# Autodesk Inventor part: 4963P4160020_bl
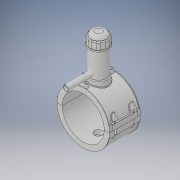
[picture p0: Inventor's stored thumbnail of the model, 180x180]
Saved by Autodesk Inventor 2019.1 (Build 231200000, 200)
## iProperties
Created: 2017-07
Part Number: 4963P4160020_bl
Material: Generic
Document SubType Name: Modeling
Designer: KIM
Density: 1 g/cm^3
Appearance: Default
Author: KIM
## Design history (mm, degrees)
derived "4963P4.ipt"
feature "Solid1::4963P4.ipt" dims "ScaleForDerivedMember" = 10
feature "Solid2::4963P4.ipt" dims "ScaleForDerivedMember" = 10
feature "Solid3::4963P4.ipt" dims "ScaleForDerivedMember" = 10
tag "TaggingFeature1"
body "Solid1"
body "Solid2"
body "Solid3"
other parameters: "d2" = 199 [user parameter], "d4" = 118 [user parameter], "d5" = 0 [user parameter], "d6" = 0.1 [user parameter], "d8" = 0 [user parameter], "d19" = 6 [user parameter], "d20" = 6 [user parameter], "d21" = 70.8 [user parameter], "d23" = 0 [user parameter], "d24" = 35.4 [user parameter], "d26" = 0 [user parameter], "d27" = 3 [user parameter], "d28" = 3 [user parameter], "d29" = 3 [user parameter], "d30" = 53.33333 [user parameter], "d31" = 6 [user parameter], "d32" = 0 [user parameter], "d33" = 0 [user parameter], "d34" = 0.6 [user parameter], "d40" = 101.504 [user parameter], "d41" = 72 [user parameter], "d43" = 0 [user parameter], "d45" = 0 [user parameter], "d47" = 168.4 [user parameter], "d70" = 15 [user parameter], "d72" = 0 [user parameter], "d73" = 6 [user parameter], "d75" = 5 [user parameter], "d76" = 0 [user parameter], "d77" = 8 [user parameter], "d79" = 15 [user parameter], "d80" = 47.2 [user parameter], "d82" = 5 deg [user parameter], "d84" = 4 [user parameter], "d85" = 14 [user parameter], "d86" = 0 [user parameter], "d87" = 3 [user parameter], "d88" = 0 [user parameter], "d89" = 1 [user parameter], "d90" = 1 [user parameter], "d91" = 94.4 [user parameter], "d92" = 0 [user parameter], "d93" = 0.5 [user parameter], "d94" = 84.21053 [user parameter], "d96" = 199.104 [user parameter], "d97" = 2.36 [user parameter], "d98" = 0 [user parameter], "d102" = 1.6 [user parameter], "d120" = 140 deg [user parameter], "d121" = 24.228 [user parameter], "d122" = 20 deg [user parameter], "d123" = 390.4 [user parameter], "d124" = 117.12 [user parameter], "d126" = 0 [user parameter], "d143" = 164.8 [user parameter], "d145" = 27.07692 [user parameter], "d149" = 2.4 [user parameter], "d150" = 29.78462 [user parameter], "d153" = 118 [user parameter], "d154" = 0 [user parameter], "d156" = 97.6 [user parameter], "d157" = 160 deg [user parameter], "d159" = 7.04 [user parameter], "d161" = 2.4 [user parameter], "d162" = 70.8 [user parameter], "d163" = 0 [user parameter], "d167" = 16 [user parameter], "d168" = 95.21951 [user parameter], "d170" = 3.75 [user parameter], "d172" = 0 [user parameter], "d173" = 1 [user parameter], "d176" = 20 deg [user parameter], "d177" = 11.2 [user parameter], "d178" = 35.2 [user parameter], "d180" = 0 [user parameter], "d183" = 14.08 [user parameter], "d184" = 8.96 [user parameter], "d185" = 38.35 [user parameter], "d186" = 38.35 [user parameter], "d187" = 97.6 [user parameter], "d188" = 10.56 [user parameter], "d189" = 11.2 [user parameter], "d190" = 0 [user parameter], "d191" = 146.4 [user parameter], "d193" = 8 [user parameter], "d194" = 4.13 [user parameter], "d195" = 90 deg [user parameter], "d197" = 0 [user parameter], "d199" = 0 [user parameter], "d200" = 17.6 [user parameter], "d202" = 0 [user parameter], "d203" = 177 [user parameter], "d204" = 68.4 [user parameter], "d205" = 50.4 [user parameter], "d206" = 61.2 [user parameter], "d207" = 132.75 [user parameter], "d208" = 138.06 [user parameter], "d209" = 164.61 [user parameter], "d210" = 61.92 [user parameter], "d211" = 72 [user parameter], "d212" = 57.6 [user parameter], "d213" = 36 [user parameter], "d216" = 0 [user parameter], "d217" = 16 [user parameter], "d218" = 16 [user parameter], "d219" = 3.2 [user parameter], "d224" = 0 [user parameter], "d227" = 16 [user parameter], "d228" = 125 [user parameter], "d230" = 3.2 [user parameter], "B_" = 199 [user parameter], "L_" = 118 [user parameter], "d_t" = 6 [user parameter], "H_2" = 177 [user parameter], "H_" = 125 [user parameter], "d1" = 195.2 [user parameter], "d148" = 2.4 [user parameter], "d160" = 2.4 [user parameter], "d169" = 3.75 [user parameter], "d192" = 8 [user parameter]
